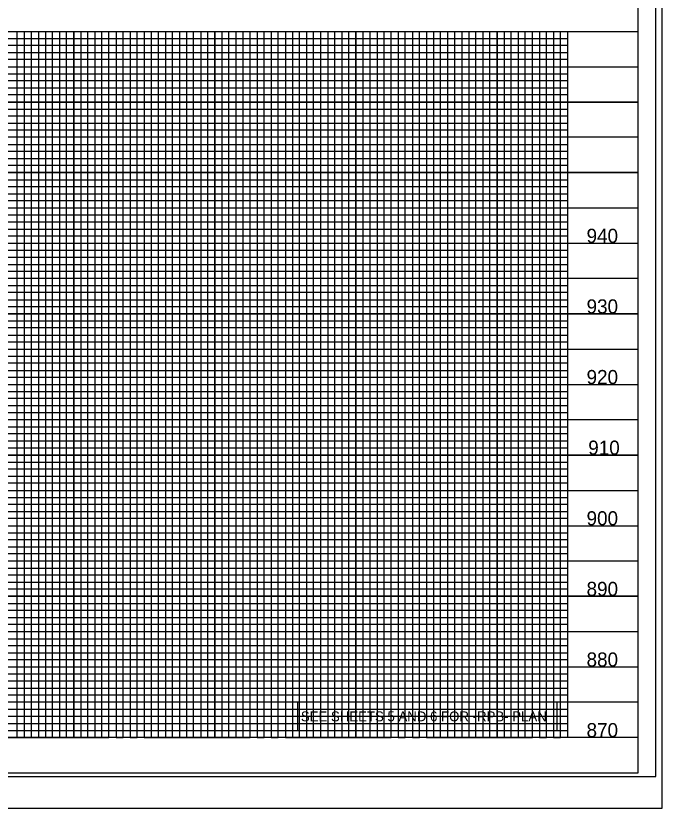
# Model space of a CAD drawing. Extents: x 1648862 to 1650715, y 820691 to 821791.
# Drawn here: x 1650088 to 1650546, y 820691 to 821252 of the extents above; entities that cross this region are included whole.
import ezdxf

# ---------------------------------------------------------------- set-up
doc = ezdxf.new("R2010")
doc.units = 0
for name, color, linetype in [('Exist Vertical Profile Vertical Axis Label', 7, 'Continuous'), ('Prop Dimension', 7, 'Continuous'), ('Prop Grid Mask', 7, 'Continuous'), ('Sheet Cutting Line CELL', 7, 'Continuous'), ('Sheet DOT Grid CELL', 7, 'Continuous'), ('Sheet Layout Profile Border Port 2', 7, 'Continuous'), ('Sheet Plot Border Inside CELL', 7, 'Continuous'), ('Sheet Plot Border Outside CELL', 7, 'Continuous'), ('Sheet Profile CELL', 7, 'Continuous'), ('Sheet Profile Grid Major CELL', 7, 'Continuous'), ('Sheet Profile Grid Middle CELL', 7, 'Continuous'), ('Sheet Profile Grid Minor CELL', 7, 'Continuous')]:
    doc.layers.add(name, color=color, linetype=linetype)

msp = doc.modelspace()

# ---------------------------------------------------------------- linework, layer by layer
at = {"layer": 'Prop Grid Mask'}
msp.add_lwpolyline([(1650287.78, 820766.02), (1650287.78, 820746.02), (1650471.78, 820746.02), (1650471.78, 820766.02)], close=True, dxfattribs=at)
at = {"layer": 'Sheet Cutting Line CELL'}
msp.add_line((1648862.28, 820691.02), (1650546.28, 820691.02), dxfattribs=at)
at = {"layer": 'Sheet DOT Grid CELL'}
for p, q in [((1649029.28, 821241.02), (1650529.17, 821241.02)), ((1650129.28, 821241.02), (1650129.28, 820741.02)), ((1650179.28, 821241.02), (1650179.28, 820741.02)), ((1650229.28, 821241.02), (1650229.28, 820741.02)), ((1650279.28, 821241.02), (1650279.28, 820741.02)), ((1650329.28, 821241.02), (1650329.28, 820741.02)), ((1650379.28, 821241.02), (1650379.28, 820741.02)), ((1650429.28, 821241.02), (1650429.28, 820741.02)), ((1650479.28, 821241.02), (1650479.28, 820741.02)), ((1649029.28, 821191.02), (1650529.17, 821191.02)), ((1649029.28, 821141.02), (1650529.17, 821141.02)), ((1649029.28, 821091.02), (1650529.17, 821091.02)), ((1649029.28, 821041.02), (1650529.17, 821041.02)), ((1649029.28, 820991.02), (1650529.17, 820991.02)), ((1649029.28, 820941.02), (1650529.17, 820941.02)), ((1649029.28, 820891.02), (1650529.17, 820891.02)), ((1649029.28, 820841.02), (1650529.17, 820841.02)), ((1649029.28, 820791.02), (1650529.17, 820791.02))]:
    msp.add_line(p, q, dxfattribs=at)
at = {"layer": 'Sheet Layout Profile Border Port 2'}
msp.add_lwpolyline([(1649079.28, 821241.02), (1650479.28, 821241.02), (1650479.28, 820741.02), (1649079.28, 820741.02)], close=True, dxfattribs=at)
at = {"layer": 'Sheet Plot Border Inside CELL'}
msp.add_lwpolyline([(1648875.28, 820713.47), (1650541.78, 820713.47), (1650541.78, 821768.57), (1648875.28, 821768.57)], close=True, dxfattribs=at)
at = {"layer": 'Sheet Plot Border Outside CELL'}
msp.add_lwpolyline([(1648862.28, 820691.02), (1650546.28, 820691.02), (1650546.28, 821791.02), (1648862.28, 821791.02)], close=True, dxfattribs=at)
at = {"layer": 'Sheet Profile CELL'}
for p, q in [((1649029.28, 821241.02), (1650529.28, 821241.02)), ((1650529.28, 820741.02), (1649029.28, 820741.02)), ((1649029.28, 820716.02), (1650529.28, 820716.02))]:
    msp.add_line(p, q, dxfattribs=at)
msp.add_lwpolyline([(1650529.28, 821766.02), (1649029.28, 821766.02), (1649029.28, 820716.02), (1650529.28, 820716.02)], close=True, dxfattribs=at)
at = {"layer": 'Sheet Profile Grid Major CELL'}
for p, q in [((1650129.28, 821241.02), (1650179.28, 821241.02)), ((1650229.28, 821241.02), (1650279.28, 821241.02)), ((1650329.28, 821241.02), (1650379.28, 821241.02)), ((1650429.28, 821241.02), (1650479.28, 821241.02)), ((1650429.28, 820741.02), (1650429.28, 820741.02))]:
    msp.add_line(p, q, dxfattribs=at)
for points in [[(1650079.28, 820741.02), (1650129.28, 820741.02), (1650129.28, 821241.02), (1650179.28, 821241.02), (1650179.28, 820741.02), (1650229.28, 820741.02), (1650229.28, 821241.02), (1650279.28, 821241.02), (1650279.28, 820741.02), (1650329.28, 820741.02), (1650329.28, 821241.02), (1650379.28, 821241.02), (1650379.28, 820741.02), (1650429.28, 820741.02), (1650429.28, 820741.02), (1650429.28, 821241.02), (1650479.28, 821241.02), (1650479.28, 820741.02)], [(1650529.28, 821191.02), (1649029.28, 821191.02)], [(1650529.28, 821141.02), (1649029.28, 821141.02), (1649029.28, 821091.02), (1650529.28, 821091.02)], [(1650529.28, 821041.02), (1649029.28, 821041.02), (1649029.28, 820991.02), (1650529.28, 820991.02)], [(1650529.28, 820941.02), (1649029.28, 820941.02), (1649029.28, 820891.02), (1650529.28, 820891.02)], [(1650529.28, 820841.02), (1649029.28, 820841.02), (1649029.28, 820841.02), (1649029.28, 820791.02), (1650529.28, 820791.02)], [(1650529.28, 820741.02), (1649029.28, 820741.02)]]:
    msp.add_lwpolyline(points, dxfattribs=at)
at = {"layer": 'Sheet Profile Grid Middle CELL'}
for points in [[(1650054.28, 821241.02), (1650104.28, 821241.02), (1650104.28, 820741.02), (1650154.28, 820741.02), (1650154.28, 821241.02), (1650204.28, 821241.02), (1650204.28, 820741.02), (1650254.28, 820741.02), (1650254.28, 821241.02), (1650304.28, 821241.02), (1650304.28, 820741.02), (1650354.28, 820741.02), (1650354.28, 821241.02), (1650404.28, 821241.02), (1650404.28, 820741.02), (1650454.28, 820741.02), (1650454.28, 821241.02)], [(1649029.28, 821216.02), (1650529.28, 821216.02)], [(1650529.28, 821166.02), (1649029.28, 821166.02), (1649029.28, 821116.02), (1650529.28, 821116.02)], [(1650529.28, 821066.02), (1649029.28, 821066.02), (1649029.28, 821016.02), (1650529.28, 821016.02)], [(1650529.28, 820966.02), (1649029.28, 820966.02), (1649029.28, 820916.02), (1650529.28, 820916.02)], [(1650529.28, 820866.02), (1649029.28, 820866.02), (1649029.28, 820816.02), (1650529.28, 820816.02)], [(1650529.28, 820766.02), (1649029.28, 820766.02)]]:
    msp.add_lwpolyline(points, dxfattribs=at)
at = {"layer": 'Sheet Profile Grid Minor CELL'}
for p, q in [((1649079.28, 821236.02), (1650479.28, 821236.02)), ((1650479.28, 821231.02), (1649079.28, 821231.02)), ((1649079.28, 821226.02), (1650479.28, 821226.02)), ((1650479.28, 821221.02), (1649079.28, 821221.02)), ((1649079.28, 821211.02), (1650479.28, 821211.02)), ((1650479.28, 821206.02), (1649079.28, 821206.02)), ((1649079.28, 821201.02), (1650479.28, 821201.02)), ((1650479.28, 821196.02), (1649079.28, 821196.02)), ((1649079.28, 821186.02), (1650479.28, 821186.02)), ((1650479.28, 821181.02), (1649079.28, 821181.02)), ((1649079.28, 821176.02), (1650479.28, 821176.02)), ((1650479.28, 821171.02), (1649079.28, 821171.02)), ((1649079.28, 821161.02), (1650479.28, 821161.02)), ((1650479.28, 821156.02), (1649079.28, 821156.02)), ((1649079.28, 821151.02), (1650479.28, 821151.02)), ((1650479.28, 821146.02), (1649079.28, 821146.02)), ((1649079.28, 821136.02), (1650479.28, 821136.02)), ((1650479.28, 821131.02), (1649079.28, 821131.02)), ((1649079.28, 821126.02), (1650479.28, 821126.02)), ((1650479.28, 821121.02), (1649079.28, 821121.02)), ((1649079.28, 821111.02), (1650479.28, 821111.02)), ((1650479.28, 821106.02), (1649079.28, 821106.02)), ((1649079.28, 821101.02), (1650479.28, 821101.02)), ((1650479.28, 821096.02), (1649079.28, 821096.02)), ((1649079.28, 821086.02), (1650479.28, 821086.02)), ((1650479.28, 821081.02), (1649079.28, 821081.02)), ((1649079.28, 821076.02), (1650479.28, 821076.02)), ((1650479.28, 821071.02), (1649079.28, 821071.02)), ((1649079.28, 821061.02), (1650479.28, 821061.02)), ((1650479.28, 821056.02), (1649079.28, 821056.02)), ((1649079.28, 821051.02), (1650479.28, 821051.02)), ((1650479.28, 821046.02), (1649079.28, 821046.17)), ((1649079.28, 821036.02), (1650479.28, 821036.02)), ((1650479.28, 821031.02), (1649079.28, 821031.02)), ((1649079.28, 821026.02), (1650479.28, 821026.02)), ((1650479.28, 821021.02), (1649079.28, 821021.02)), ((1649079.28, 821011.02), (1650479.28, 821011.02)), ((1650479.28, 821006.02), (1649079.28, 821006.02)), ((1649079.28, 821001.02), (1650479.28, 821001.02)), ((1650479.28, 820996.02), (1649079.28, 820996.02)), ((1649079.28, 820986.02), (1650479.28, 820986.02)), ((1650479.28, 820981.02), (1649079.28, 820981.02)), ((1649079.28, 820976.02), (1650479.28, 820976.02)), ((1650479.28, 820971.02), (1649079.28, 820971.02)), ((1649079.28, 820961.02), (1650479.28, 820961.02)), ((1650479.28, 820956.02), (1649079.28, 820956.02)), ((1649079.28, 820951.02), (1650479.28, 820951.02)), ((1650479.28, 820946.02), (1649079.28, 820946.02)), ((1649079.28, 820936.02), (1650479.28, 820936.02)), ((1650479.28, 820931.02), (1649079.28, 820931.02)), ((1649079.28, 820926.02), (1650479.28, 820926.02)), ((1650479.28, 820921.02), (1649079.28, 820921.02)), ((1649079.28, 820911.02), (1650479.28, 820911.02)), ((1650479.28, 820906.02), (1649079.28, 820906.02)), ((1649079.28, 820901.02), (1650479.28, 820901.02)), ((1650479.28, 820896.02), (1649079.28, 820896.02)), ((1649079.28, 820886.02), (1650479.28, 820886.02)), ((1650479.28, 820881.02), (1649079.28, 820881.02)), ((1649079.28, 820876.02), (1650479.28, 820876.02)), ((1650479.28, 820871.02), (1649079.28, 820871.02)), ((1649079.28, 820861.02), (1650479.28, 820861.02)), ((1650479.28, 820856.02), (1649079.28, 820856.02)), ((1649079.28, 820851.02), (1650479.28, 820851.02)), ((1650479.28, 820846.02), (1649079.28, 820846.02)), ((1649079.28, 820836.02), (1650479.28, 820836.02)), ((1650479.28, 820831.02), (1649079.28, 820831.02)), ((1649079.28, 820826.02), (1650479.28, 820826.02)), ((1650479.28, 820821.02), (1649079.28, 820821.02)), ((1649079.28, 820811.02), (1650479.28, 820811.02)), ((1650479.28, 820806.02), (1649079.28, 820806.02)), ((1649079.28, 820801.02), (1650479.28, 820801.02)), ((1650479.28, 820796.02), (1649079.28, 820796.02)), ((1649079.28, 820786.02), (1650479.28, 820786.02)), ((1650479.28, 820781.02), (1649079.28, 820781.02)), ((1649079.28, 820776.02), (1650479.28, 820776.02)), ((1650479.28, 820771.02), (1649079.28, 820771.02)), ((1649079.28, 820761.02), (1650479.28, 820761.02)), ((1650479.28, 820756.02), (1649079.28, 820756.02)), ((1649079.28, 820751.02), (1650479.28, 820751.02)), ((1649079.28, 820746.02), (1650479.28, 820746.02)), ((1650479.28, 820746.02), (1650479.28, 820746.02))]:
    msp.add_line(p, q, dxfattribs=at)
for points in [[(1650084.28, 820741.02), (1650089.28, 820741.02), (1650089.28, 821241.02), (1650094.28, 821241.02), (1650094.28, 820741.02), (1650099.28, 820741.02), (1650099.28, 821241.02), (1650109.28, 821241.02), (1650109.28, 820741.02), (1650114.28, 820741.02), (1650114.28, 821241.02), (1650119.28, 821241.02), (1650119.28, 820741.02), (1650124.28, 820741.02), (1650124.28, 821241.02), (1650134.28, 821241.02), (1650134.28, 820741.02), (1650139.28, 820741.02), (1650139.28, 821241.02), (1650144.28, 821241.02), (1650144.28, 820741.02), (1650149.28, 820741.02), (1650149.28, 821241.02), (1650159.28, 821241.02), (1650159.28, 820741.02), (1650164.28, 820741.02), (1650164.28, 821241.02), (1650169.28, 821241.02), (1650169.28, 820741.02), (1650174.28, 820741.02), (1650174.28, 821241.02), (1650184.28, 821241.02), (1650184.28, 820741.02), (1650189.28, 820741.02), (1650189.28, 821241.02), (1650194.28, 821241.02), (1650194.28, 820741.02), (1650199.28, 820741.02), (1650199.28, 821241.02), (1650209.28, 821241.02), (1650209.28, 820741.02), (1650214.28, 820741.02), (1650214.28, 821241.02), (1650219.28, 821241.02), (1650219.28, 820741.02)], [(1650219.28, 820741.02), (1650224.28, 820741.02), (1650224.28, 821241.02), (1650234.28, 821241.02), (1650234.28, 820741.02), (1650239.28, 820741.02), (1650239.28, 821241.02), (1650244.28, 821241.02), (1650244.28, 820741.02), (1650249.28, 820741.02), (1650249.28, 821241.02), (1650259.28, 821241.02), (1650259.28, 820741.02), (1650264.28, 820741.02), (1650264.28, 821241.02), (1650269.28, 821241.02), (1650269.28, 820741.02), (1650274.28, 820741.02), (1650274.28, 821241.02), (1650284.28, 821241.02), (1650284.28, 820741.02), (1650289.28, 820741.02), (1650289.28, 821241.02), (1650294.28, 821241.02), (1650294.28, 820741.02), (1650299.28, 820741.02), (1650299.28, 821241.02), (1650309.28, 821241.02), (1650309.28, 820741.02), (1650314.28, 820741.02), (1650314.28, 821241.02), (1650319.28, 821241.02), (1650319.28, 820741.02), (1650324.28, 820741.02), (1650324.28, 821241.02), (1650334.28, 821241.02), (1650334.28, 820741.02), (1650339.28, 820741.02), (1650339.28, 821241.02), (1650344.28, 821241.02), (1650344.28, 820741.02), (1650349.28, 820741.02), (1650349.28, 821241.02), (1650359.28, 821241.02), (1650359.28, 820741.02), (1650364.28, 820741.02), (1650364.28, 821241.02), (1650369.28, 821241.02), (1650369.28, 820741.02), (1650374.28, 820741.02), (1650374.28, 821241.02), (1650384.28, 821241.02), (1650384.28, 820741.02), (1650389.28, 820741.02), (1650389.28, 821241.02), (1650394.28, 821241.02), (1650394.28, 820741.02), (1650399.28, 820741.02), (1650399.28, 821241.02), (1650409.28, 821241.02), (1650409.28, 820741.02), (1650414.28, 820741.02), (1650414.28, 821241.02), (1650419.28, 821241.02), (1650419.28, 820741.02), (1650424.28, 820741.02), (1650424.28, 821241.02), (1650434.28, 821241.02), (1650434.28, 820741.02), (1650439.28, 820741.02), (1650439.28, 821241.02), (1650444.28, 821241.02), (1650444.28, 820741.02), (1650449.28, 820741.02), (1650449.28, 821241.02), (1650459.28, 821241.02), (1650459.28, 820741.02), (1650464.28, 820741.02), (1650464.28, 821241.02), (1650469.28, 821241.02), (1650469.28, 820741.02), (1650474.28, 820741.02), (1650474.28, 821241.02), (1650479.28, 821241.02)]]:
    msp.add_lwpolyline(points, dxfattribs=at)

# ---------------------------------------------------------------- texts
at = {"layer": 'Exist Vertical Profile Vertical Axis Label'}
for s, p in [('940', (1650492.71, 821091.27)), ('930', (1650492.71, 821041.27)), ('920', (1650492.71, 820991.27)), ('910', (1650493.91, 820941.27)), ('900', (1650492.71, 820891.27)), ('890', (1650492.71, 820841.27)), ('880', (1650492.71, 820791.27)), ('870', (1650492.71, 820741.27))]:
    msp.add_text(s, height=10, dxfattribs=at).set_placement(p)
at = {"layer": 'Prop Dimension'}
msp.add_text('SEE SHEETS 5 AND 6 FOR -RPB- PLAN', height=7, dxfattribs=at).set_placement((1650290.25, 820752.52))

doc.saveas('drawing.dxf')
